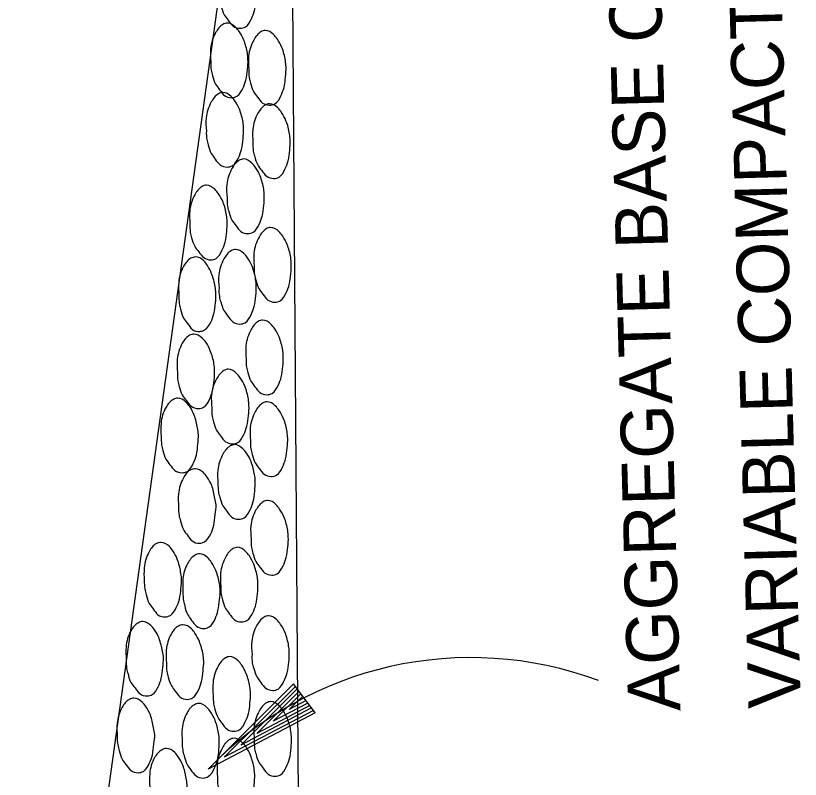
# Model space of a CAD drawing. Extents: x 1926836 to 1933254, y 596317 to 604524.
# Drawn here: x 1932679.1 to 1932768.9, y 597557.2 to 597644.8 of the extents above; entities that cross this region are included whole.
import ezdxf

# ---------------------------------------------------------------- set-up
doc = ezdxf.new("R2010")
doc.units = 0
doc.layers.add('Default', color=7, linetype='Continuous')

msp = doc.modelspace()

# ---------------------------------------------------------------- linework, layer by layer
at = {"layer": 'Default'}
for p, q in [((1932679.061, 597479.649), (1932733.749, 597872.488)), ((1932713.685, 597228.788), (1932710.428, 597704.892)), ((1932710.897, 597568.165), (1932701.106, 597558.399)), ((1932711.145, 597567.892), (1932702.94, 597559.768)), ((1932711.322, 597567.606), (1932704.853, 597561.16)), ((1932711.55, 597567.322), (1932706.688, 597562.5)), ((1932713.357, 597564.85), (1932710.897, 597568.165)), ((1932711.737, 597567.047), (1932708.551, 597563.891)), ((1932711.955, 597566.763), (1932710.375, 597565.24)), ((1932712.744, 597565.704), (1932706.688, 597562.5)), ((1932712.516, 597565.978), (1932708.551, 597563.891)), ((1932712.339, 597566.253), (1932710.375, 597565.24)), ((1932713.357, 597564.85), (1932701.106, 597558.399)), ((1932713.17, 597565.125), (1932702.94, 597559.768)), ((1932712.952, 597565.419), (1932704.853, 597561.16))]:
    msp.add_line(p, q, dxfattribs=at)
msp.add_arc((1932731.211, 597529.351), 41.833, 69.53091, 136.01985, dxfattribs=at)
for points in [[(1932702.397, 597647.445), (1932702.366, 597648.955), (1932702.957, 597650.802), (1932703.792, 597651.744), (1932704.288, 597651.898), (1932705.231, 597651.423), (1932705.675, 597650.905), (1932706.181, 597649.948), (1932706.591, 597648.448), (1932706.661, 597647.72), (1932706.611, 597646.578), (1932706.424, 597645.363), (1932706.06, 597644.403), (1932705.384, 597643.494), (1932704.768, 597643.338), (1932703.981, 597643.577), (1932703.403, 597644.251), (1932702.945, 597644.889), (1932702.599, 597645.86), (1932702.432, 597646.486), (1932702.397, 597647.445)], [(1932701.41, 597639.486), (1932701.389, 597640.996), (1932701.97, 597642.842), (1932702.805, 597643.785), (1932703.301, 597643.938), (1932704.244, 597643.464), (1932704.688, 597642.945), (1932705.194, 597641.989), (1932705.604, 597640.489), (1932705.674, 597639.761), (1932705.625, 597638.619), (1932705.438, 597637.393), (1932705.073, 597636.433), (1932704.397, 597635.535), (1932703.781, 597635.378), (1932702.994, 597635.617), (1932702.416, 597636.292), (1932701.959, 597636.93), (1932701.613, 597637.901), (1932701.456, 597638.527), (1932701.41, 597639.486)], [(1932705.764, 597638.643), (1932705.744, 597640.153), (1932706.334, 597641.989), (1932707.16, 597642.932), (1932707.656, 597643.085), (1932708.609, 597642.61), (1932709.043, 597642.092), (1932709.548, 597641.145), (1932709.959, 597639.636), (1932710.029, 597638.907), (1932709.979, 597637.765), (1932709.802, 597636.55), (1932709.437, 597635.59), (1932708.751, 597634.681), (1932708.135, 597634.525), (1932707.349, 597634.764), (1932706.77, 597635.439), (1932706.313, 597636.076), (1932705.967, 597637.058), (1932705.81, 597637.674), (1932705.764, 597638.643)], [(1932700.903, 597631.54), (1932700.882, 597633.05), (1932701.473, 597634.886), (1932702.298, 597635.829), (1932702.794, 597635.982), (1932703.747, 597635.517), (1932704.181, 597634.999), (1932704.687, 597634.042), (1932705.108, 597632.543), (1932705.167, 597631.814), (1932705.118, 597630.672), (1932704.941, 597629.447), (1932704.576, 597628.487), (1932703.9, 597627.579), (1932703.274, 597627.422), (1932702.487, 597627.671), (1932701.909, 597628.336), (1932701.462, 597628.984), (1932701.106, 597629.955), (1932700.949, 597630.571), (1932700.903, 597631.54)], [(1932706.24, 597630.232), (1932706.219, 597631.742), (1932706.81, 597633.589), (1932707.635, 597634.521), (1932708.131, 597634.675), (1932709.084, 597634.21), (1932709.518, 597633.692), (1932710.024, 597632.735), (1932710.435, 597631.235), (1932710.504, 597630.507), (1932710.455, 597629.365), (1932710.268, 597628.14), (1932709.903, 597627.18), (1932709.227, 597626.271), (1932708.611, 597626.115), (1932707.824, 597626.364), (1932707.246, 597627.028), (1932706.789, 597627.676), (1932706.443, 597628.647), (1932706.286, 597629.263), (1932706.24, 597630.232)], [(1932703.279, 597623.901), (1932703.248, 597625.41), (1932703.839, 597627.257), (1932704.674, 597628.2), (1932705.17, 597628.353), (1932706.113, 597627.878), (1932706.547, 597627.36), (1932707.063, 597626.403), (1932707.473, 597624.904), (1932707.543, 597624.175), (1932707.494, 597623.033), (1932707.306, 597621.808), (1932706.942, 597620.848), (1932706.266, 597619.949), (1932705.65, 597619.793), (1932704.863, 597620.032), (1932704.285, 597620.707), (1932703.828, 597621.344), (1932703.471, 597622.315), (1932703.315, 597622.941), (1932703.279, 597623.901)], [(1932699.028, 597620.906), (1932698.997, 597622.415), (1932699.588, 597624.252), (1932700.423, 597625.195), (1932700.919, 597625.348), (1932701.862, 597624.873), (1932702.296, 597624.354), (1932702.812, 597623.408), (1932703.222, 597621.908), (1932703.292, 597621.17), (1932703.242, 597620.038), (1932703.055, 597618.813), (1932702.691, 597617.853), (1932702.015, 597616.944), (1932701.399, 597616.788), (1932700.612, 597617.037), (1932700.034, 597617.701), (1932699.576, 597618.349), (1932699.22, 597619.32), (1932699.064, 597619.936), (1932699.028, 597620.906)], [(1932706.371, 597616.051), (1932706.35, 597617.561), (1932706.941, 597619.397), (1932707.766, 597620.34), (1932708.262, 597620.493), (1932709.215, 597620.029), (1932709.649, 597619.51), (1932710.155, 597618.553), (1932710.565, 597617.054), (1932710.635, 597616.325), (1932710.585, 597615.184), (1932710.408, 597613.958), (1932710.044, 597612.998), (1932709.358, 597612.09), (1932708.742, 597611.933), (1932707.955, 597612.182), (1932707.377, 597612.847), (1932706.919, 597613.495), (1932706.573, 597614.466), (1932706.417, 597615.082), (1932706.371, 597616.051)], [(1932702.356, 597613.542), (1932702.326, 597615.052), (1932702.917, 597616.888), (1932703.752, 597617.831), (1932704.248, 597617.985), (1932705.191, 597617.52), (1932705.625, 597617.001), (1932706.141, 597616.045), (1932706.551, 597614.545), (1932706.621, 597613.817), (1932706.571, 597612.675), (1932706.384, 597611.45), (1932706.02, 597610.489), (1932705.344, 597609.581), (1932704.728, 597609.424), (1932703.941, 597609.673), (1932703.363, 597610.338), (1932702.905, 597610.986), (1932702.549, 597611.957), (1932702.392, 597612.573), (1932702.356, 597613.542)], [(1932697.767, 597612.699), (1932697.737, 597614.208), (1932698.298, 597616.054), (1932699.133, 597616.967), (1932699.629, 597617.12), (1932700.602, 597616.676), (1932701.026, 597616.137), (1932701.512, 597615.19), (1932701.911, 597613.73), (1932701.992, 597612.952), (1932701.952, 597611.851), (1932701.775, 597610.596), (1932701.401, 597609.635), (1932700.705, 597608.746), (1932700.139, 597608.571), (1932699.303, 597608.799), (1932698.753, 597609.504), (1932698.287, 597610.112), (1932697.949, 597611.133), (1932697.802, 597611.769), (1932697.767, 597612.699)], [(1932705.455, 597605.442), (1932705.434, 597606.952), (1932706.025, 597608.789), (1932706.85, 597609.731), (1932707.346, 597609.885), (1932708.299, 597609.41), (1932708.734, 597608.892), (1932709.239, 597607.945), (1932709.649, 597606.445), (1932709.719, 597605.707), (1932709.67, 597604.575), (1932709.492, 597603.35), (1932709.128, 597602.39), (1932708.442, 597601.481), (1932707.826, 597601.325), (1932707.039, 597601.574), (1932706.461, 597602.238), (1932706.004, 597602.886), (1932705.658, 597603.857), (1932705.501, 597604.473), (1932705.455, 597605.442)], [(1932697.594, 597603.871), (1932697.574, 597605.381), (1932698.144, 597607.227), (1932698.99, 597608.14), (1932699.477, 597608.273), (1932700.419, 597607.818), (1932700.873, 597607.31), (1932701.359, 597606.343), (1932701.779, 597604.874), (1932701.849, 597604.125), (1932701.799, 597603.003), (1932701.612, 597601.768), (1932701.269, 597600.778), (1932700.582, 597599.89), (1932699.996, 597599.744), (1932699.179, 597599.992), (1932698.601, 597600.657), (1932698.133, 597601.304), (1932697.797, 597602.276), (1932697.64, 597602.912), (1932697.594, 597603.871)], [(1932701.525, 597599.805), (1932701.494, 597601.315), (1932702.085, 597603.151), (1932702.92, 597604.094), (1932703.416, 597604.247), (1932704.359, 597603.772), (1932704.793, 597603.254), (1932705.309, 597602.307), (1932705.719, 597600.808), (1932705.789, 597600.069), (1932705.74, 597598.938), (1932705.552, 597597.712), (1932705.188, 597596.752), (1932704.512, 597595.844), (1932703.896, 597595.687), (1932703.109, 597595.936), (1932702.531, 597596.601), (1932702.074, 597597.249), (1932701.717, 597598.22), (1932701.561, 597598.836), (1932701.525, 597599.805)], [(1932695.731, 597596.528), (1932695.71, 597598.038), (1932696.281, 597599.884), (1932697.137, 597600.788), (1932697.623, 597600.941), (1932698.556, 597600.476), (1932699.009, 597599.967), (1932699.506, 597598.98), (1932699.906, 597597.511), (1932699.996, 597596.773), (1932699.935, 597595.661), (1932699.769, 597594.406), (1932699.405, 597593.446), (1932698.729, 597592.537), (1932698.133, 597592.381), (1932697.306, 597592.639), (1932696.738, 597593.294), (1932696.27, 597593.942), (1932695.933, 597594.933), (1932695.776, 597595.579), (1932695.731, 597596.528)], [(1932705.957, 597596.073), (1932705.936, 597597.583), (1932706.527, 597599.419), (1932707.352, 597600.362), (1932707.848, 597600.515), (1932708.801, 597600.04), (1932709.235, 597599.522), (1932709.741, 597598.575), (1932710.151, 597597.075), (1932710.221, 597596.337), (1932710.171, 597595.205), (1932709.984, 597593.98), (1932709.63, 597593.02), (1932708.944, 597592.111), (1932708.328, 597591.955), (1932707.541, 597592.204), (1932706.963, 597592.868), (1932706.505, 597593.516), (1932706.159, 597594.487), (1932706.003, 597595.103), (1932705.957, 597596.073)], [(1932702.237, 597591.151), (1932702.217, 597592.661), (1932702.807, 597594.507), (1932703.632, 597595.45), (1932704.128, 597595.603), (1932705.082, 597595.129), (1932705.516, 597594.61), (1932706.021, 597593.653), (1932706.432, 597592.154), (1932706.501, 597591.425), (1932706.452, 597590.284), (1932706.275, 597589.069), (1932705.91, 597588.108), (1932705.224, 597587.2), (1932704.608, 597587.043), (1932703.822, 597587.282), (1932703.243, 597587.957), (1932702.796, 597588.595), (1932702.44, 597589.566), (1932702.283, 597590.192), (1932702.237, 597591.151)], [(1932697.729, 597588.429), (1932697.707, 597589.969), (1932698.279, 597591.795), (1932699.114, 597592.708), (1932699.621, 597592.831), (1932700.573, 597592.387), (1932700.987, 597591.888), (1932701.513, 597590.931), (1932701.883, 597589.441), (1932702.013, 597588.704), (1932701.913, 597587.571), (1932701.746, 597586.356), (1932701.412, 597585.377), (1932700.706, 597584.467), (1932700.12, 597584.302), (1932699.283, 597584.559), (1932698.735, 597585.225), (1932698.277, 597585.873), (1932697.941, 597586.844), (1932697.774, 597587.48), (1932697.729, 597588.429)], [(1932706.03, 597584.75), (1932706, 597586.27), (1932706.591, 597588.107), (1932707.426, 597589.049), (1932707.922, 597589.203), (1932708.865, 597588.728), (1932709.299, 597588.209), (1932709.815, 597587.253), (1932710.225, 597585.753), (1932710.295, 597585.025), (1932710.245, 597583.883), (1932710.058, 597582.668), (1932709.693, 597581.708), (1932709.017, 597580.799), (1932708.401, 597580.643), (1932707.615, 597580.882), (1932707.036, 597581.556), (1932706.579, 597582.194), (1932706.223, 597583.175), (1932706.066, 597583.791), (1932706.03, 597584.75)], [(1932693.794, 597579.98), (1932693.784, 597581.481), (1932694.345, 597583.316), (1932695.19, 597584.259), (1932695.687, 597584.383), (1932696.648, 597583.958), (1932697.052, 597583.439), (1932697.578, 597582.473), (1932697.958, 597581.002), (1932698.059, 597580.235), (1932697.999, 597579.103), (1932697.812, 597577.867), (1932697.457, 597576.918), (1932696.781, 597576.029), (1932696.196, 597575.853), (1932695.359, 597576.101), (1932694.81, 597576.786), (1932694.364, 597577.395), (1932693.996, 597578.415), (1932693.849, 597579.051), (1932693.794, 597579.98)], [(1932702.553, 597579.375), (1932702.533, 597580.885), (1932703.123, 597582.732), (1932703.948, 597583.674), (1932704.445, 597583.828), (1932705.398, 597583.353), (1932705.832, 597582.834), (1932706.338, 597581.878), (1932706.748, 597580.378), (1932706.818, 597579.65), (1932706.768, 597578.508), (1932706.591, 597577.283), (1932706.227, 597576.323), (1932705.54, 597575.424), (1932704.924, 597575.267), (1932704.138, 597575.506), (1932703.559, 597576.181), (1932703.112, 597576.819), (1932702.756, 597577.79), (1932702.599, 597578.416), (1932702.553, 597579.375)], [(1932698.221, 597578.669), (1932698.22, 597580.199), (1932698.771, 597582.005), (1932699.637, 597582.928), (1932700.113, 597583.081), (1932701.066, 597582.626), (1932701.5, 597582.088), (1932701.996, 597581.151), (1932702.406, 597579.651), (1932702.485, 597578.923), (1932702.426, 597577.801), (1932702.228, 597576.575), (1932701.904, 597575.606), (1932701.218, 597574.698), (1932700.613, 597574.521), (1932699.766, 597574.779), (1932699.217, 597575.454), (1932698.78, 597576.093), (1932698.423, 597577.104), (1932698.287, 597577.7), (1932698.221, 597578.669)], [(1932706.135, 597571.538), (1932706.104, 597573.048), (1932706.695, 597574.895), (1932707.53, 597575.827), (1932708.026, 597575.981), (1932708.969, 597575.516), (1932709.403, 597574.997), (1932709.919, 597574.041), (1932710.33, 597572.541), (1932710.399, 597571.813), (1932710.35, 597570.671), (1932710.163, 597569.446), (1932709.798, 597568.486), (1932709.122, 597567.577), (1932708.506, 597567.421), (1932707.719, 597567.67), (1932707.141, 597568.334), (1932706.684, 597568.982), (1932706.328, 597569.953), (1932706.171, 597570.569), (1932706.135, 597571.538)], [(1932691.727, 597570.902), (1932691.706, 597572.412), (1932692.267, 597574.267), (1932693.113, 597575.18), (1932693.619, 597575.314), (1932694.552, 597574.859), (1932694.975, 597574.36), (1932695.481, 597573.393), (1932695.881, 597571.913), (1932695.992, 597571.156), (1932695.911, 597570.044), (1932695.744, 597568.829), (1932695.381, 597567.819), (1932694.704, 597566.95), (1932694.118, 597566.784), (1932693.281, 597567.052), (1932692.733, 597567.707), (1932692.266, 597568.325), (1932691.929, 597569.316), (1932691.772, 597569.952), (1932691.727, 597570.902)], [(1932696.338, 597570.545), (1932696.318, 597572.055), (1932696.869, 597573.881), (1932697.704, 597574.803), (1932698.221, 597574.947), (1932699.193, 597574.483), (1932699.587, 597573.994), (1932700.103, 597573.027), (1932700.522, 597571.558), (1932700.603, 597570.8), (1932700.523, 597569.687), (1932700.356, 597568.442), (1932699.992, 597567.462), (1932699.326, 597566.554), (1932698.73, 597566.398), (1932697.893, 597566.656), (1932697.344, 597567.341), (1932696.908, 597567.96), (1932696.541, 597568.94), (1932696.384, 597569.596), (1932696.338, 597570.545)], [(1932701.689, 597566.847), (1932701.668, 597568.367), (1932702.259, 597570.204), (1932703.084, 597571.146), (1932703.58, 597571.3), (1932704.533, 597570.825), (1932704.968, 597570.307), (1932705.473, 597569.35), (1932705.894, 597567.851), (1932705.953, 597567.122), (1932705.904, 597565.98), (1932705.727, 597564.765), (1932705.362, 597563.805), (1932704.676, 597562.896), (1932704.06, 597562.74), (1932703.274, 597562.979), (1932702.695, 597563.653), (1932702.248, 597564.292), (1932701.892, 597565.272), (1932701.735, 597565.888), (1932701.689, 597566.847)], [(1932690.692, 597562.141), (1932690.681, 597563.641), (1932691.252, 597565.497), (1932692.088, 597566.38), (1932692.594, 597566.533), (1932693.547, 597566.089), (1932693.96, 597565.58), (1932694.487, 597564.603), (1932694.866, 597563.143), (1932694.987, 597562.386), (1932694.886, 597561.273), (1932694.72, 597560.008), (1932694.356, 597559.048), (1932693.69, 597558.14), (1932693.094, 597557.984), (1932692.256, 597558.261), (1932691.698, 597558.927), (1932691.241, 597559.544), (1932690.915, 597560.526), (1932690.747, 597561.182), (1932690.692, 597562.141)], [(1932698.141, 597561.53), (1932698.13, 597563.051), (1932698.691, 597564.866), (1932699.537, 597565.779), (1932700.003, 597565.932), (1932700.966, 597565.458), (1932701.38, 597564.958), (1932701.896, 597564.002), (1932702.305, 597562.522), (1932702.386, 597561.774), (1932702.345, 597560.663), (1932702.168, 597559.428), (1932701.804, 597558.458), (1932701.129, 597557.549), (1932700.523, 597557.373), (1932699.695, 597557.651), (1932699.117, 597558.315), (1932698.69, 597558.944), (1932698.354, 597559.915), (1932698.196, 597560.571), (1932698.141, 597561.53)], [(1932706.399, 597561.692), (1932706.369, 597563.202), (1932706.959, 597565.048), (1932707.794, 597565.991), (1932708.29, 597566.144), (1932709.234, 597565.67), (1932709.668, 597565.151), (1932710.183, 597564.194), (1932710.594, 597562.695), (1932710.663, 597561.967), (1932710.614, 597560.825), (1932710.427, 597559.599), (1932710.062, 597558.639), (1932709.386, 597557.741), (1932708.77, 597557.584), (1932707.984, 597557.823), (1932707.405, 597558.498), (1932706.948, 597559.136), (1932706.592, 597560.107), (1932706.435, 597560.733), (1932706.399, 597561.692)], [(1932702.18, 597557.497), (1932702.15, 597559.007), (1932702.741, 597560.844), (1932703.576, 597561.786), (1932704.072, 597561.94), (1932705.015, 597561.465), (1932705.449, 597560.956), (1932705.955, 597559.999), (1932706.375, 597558.5), (1932706.444, 597557.772), (1932706.395, 597556.63), (1932706.208, 597555.405), (1932705.844, 597554.444), (1932705.168, 597553.536), (1932704.552, 597553.379), (1932703.765, 597553.628), (1932703.187, 597554.293), (1932702.729, 597554.941), (1932702.373, 597555.912), (1932702.216, 597556.528), (1932702.18, 597557.497)], [(1932694.428, 597556.349), (1932694.418, 597557.869), (1932694.978, 597559.715), (1932695.824, 597560.628), (1932696.32, 597560.771), (1932697.283, 597560.307), (1932697.687, 597559.808), (1932698.213, 597558.841), (1932698.592, 597557.371), (1932698.692, 597556.623), (1932698.633, 597555.501), (1932698.446, 597554.266), (1932698.092, 597553.286), (1932697.416, 597552.378), (1932696.829, 597552.242), (1932695.993, 597552.469), (1932695.444, 597553.155), (1932694.997, 597553.783), (1932694.631, 597554.764), (1932694.483, 597555.42), (1932694.428, 597556.349)]]:
    msp.add_spline(points, degree=3, dxfattribs=at)

# ---------------------------------------------------------------- texts
for s, p in [('AGGREGATE BASE COURSE (CLASS 7)', (1932755.226, 597565.086)), ('VARIABLE COMPACTED DEPTH', (1932769.011, 597565.456))]:
    msp.add_text(s, height=6.00001, rotation=91.53769, dxfattribs=at).set_placement(p)

doc.saveas('drawing.dxf')
